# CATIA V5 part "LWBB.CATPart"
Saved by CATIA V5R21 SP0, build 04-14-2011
Part number: LWBB.SLDPRT
Bounding box of the stored display mesh (mm): x 1.55 to 5.05, y 3.678 to 6.478, z -1.805 to -0.004
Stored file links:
  C:\Users\user\Desktop\LWBB\LWBB.CATPart
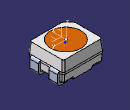
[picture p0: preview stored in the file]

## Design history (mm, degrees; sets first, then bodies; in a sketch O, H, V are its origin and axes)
AxisSystem1: origin (3.2985, 5.0752, -0.0046), X (0, -1, 0), Y (1, 0, 0), Z (0, 0, 1)
Set1
  DatumSurface1 to DatumSurface120
  Line1: stored without definition
  Circle1: stored without definition
  Line2: stored without definition
  Circle2: stored without definition
  Line3 to Line38: stored without definition
  Circle3: stored without definition
  Line39: stored without definition
  Circle4: stored without definition
  Line40 to Line43: stored without definition
  Circle5: stored without definition
  Circle6: stored without definition
  Line44 to Line46: stored without definition
  Circle7: stored without definition
  Line47: stored without definition
  Circle8: stored without definition
  Line48 to Line50: stored without definition
  Circle9 to Circle11: stored without definition
  Line51: stored without definition
  Circle12: stored without definition
  Line52: stored without definition
  Circle13 to Circle15: stored without definition
  Line53: stored without definition
  Circle16: stored without definition
  Line54: stored without definition
  Circle17 to Circle19: stored without definition
  Line55: stored without definition
  Circle20: stored without definition
  Line56: stored without definition
  Circle21 to Circle23: stored without definition
  Line57: stored without definition
  Circle24: stored without definition
  Line58: stored without definition
  Circle25: stored without definition
  Circle26: stored without definition
  Line59 to Line62: stored without definition
  Circle27: stored without definition
  Circle28: stored without definition
  Line63 to Line66: stored without definition
  Circle29: stored without definition
  Circle30: stored without definition
  Line67: stored without definition
  Circle31: stored without definition
  Line68: stored without definition
  Circle32: stored without definition
  Line69 to Line72: stored without definition
  Circle33: stored without definition
  Line73: stored without definition
  Circle34: stored without definition
  Circle35: stored without definition
  Line74: stored without definition
  Circle36: stored without definition
  Line75 to Line78: stored without definition
  Circle37: stored without definition
  Line79: stored without definition
  Circle38: stored without definition
  Line80 to Line82: stored without definition
  Circle39: stored without definition
  Line83: stored without definition
  Circle40: stored without definition
  Line84 to Line86: stored without definition
  Circle41: stored without definition
  Line87: stored without definition
  Circle42: stored without definition
  Line88 to Line90: stored without definition
  Circle43: stored without definition
  Line91: stored without definition
  Circle44: stored without definition
  Circle45: stored without definition
  Line92: stored without definition
  Circle46: stored without definition
  Line93 to Line95: stored without definition
  Circle47: stored without definition
  Line96: stored without definition
  Circle48: stored without definition
  Circle49: stored without definition
  Line97: stored without definition
  Circle50: stored without definition
  Line98 to Line100: stored without definition
  Circle51: stored without definition
  Line101: stored without definition
  Circle52: stored without definition
  Line102 to Line104: stored without definition
  Circle53: stored without definition
  Line105: stored without definition
  Circle54: stored without definition
  Line106 to Line108: stored without definition
  Circle55: stored without definition
  Line109: stored without definition
  Circle56: stored without definition
  Line110 to Line112: stored without definition
  Circle57: stored without definition
  Line113: stored without definition
  Circle58: stored without definition
  Line114: stored without definition
  Circle59: stored without definition
  Line115: stored without definition
  Circle60: stored without definition
  Line116 to Line118: stored without definition
  Circle61: stored without definition
  Line119: stored without definition
  Circle62: stored without definition
  Line120 to Line132: stored without definition
  Circle63: stored without definition
  Line133: stored without definition
  Circle64: stored without definition
  Line134 to Line136: stored without definition
  Circle65: stored without definition
  Line137: stored without definition
  Circle66: stored without definition
  Line138: stored without definition
  Circle67: stored without definition
  Line139: stored without definition
  Circle68: stored without definition
  Line140 to Line143: stored without definition
  Circle69: stored without definition
  Circle70: stored without definition
  Line144 to Line153: stored without definition
  Circle71: stored without definition
  Line154: stored without definition
  Circle72: stored without definition
  Line155 to Line157: stored without definition
  Circle73: stored without definition
  Line158: stored without definition
  Circle74: stored without definition
  Line159 to Line161: stored without definition
  Circle75: stored without definition
  Line162: stored without definition
  Circle76: stored without definition
  Line163 to Line165: stored without definition
  Circle77: stored without definition
  Line166: stored without definition
  Circle78: stored without definition
  Line167 to Line169: stored without definition
  Circle79: stored without definition
  Line170: stored without definition
  Circle80: stored without definition
  Line171 to Line173: stored without definition
  Circle81: stored without definition
  Line174: stored without definition
  Circle82: stored without definition
  Line175 to Line177: stored without definition
  Circle83: stored without definition
  Line178: stored without definition
  Circle84: stored without definition
  Line179 to Line181: stored without definition
  Circle85: stored without definition
  Line182: stored without definition
  Circle86: stored without definition
  Line183 to Line185: stored without definition
  Circle87: stored without definition
  Line186: stored without definition
  Circle88: stored without definition
  Line187 to Line189: stored without definition
  Circle89: stored without definition
  Line190: stored without definition
  Circle90: stored without definition
  Line191 to Line193: stored without definition
  Circle91: stored without definition
  Line194: stored without definition
  Circle92: stored without definition
  Line195 to Line197: stored without definition
  Circle93: stored without definition
  Line198: stored without definition
  Circle94: stored without definition
  Line199 to Line201: stored without definition
  Circle95: stored without definition
  Line202: stored without definition
  Circle96: stored without definition
  Line203 to Line205: stored without definition
  Circle97: stored without definition
  Line206: stored without definition
  Circle98: stored without definition
  Line207 to Line209: stored without definition
  Circle99: stored without definition
  Line210: stored without definition
  Circle100: stored without definition
  Line211 to Line213: stored without definition
  Circle101: stored without definition
  Line214: stored without definition
  Circle102: stored without definition
  Line215 to Line217: stored without definition
  Circle103: stored without definition
  Line218: stored without definition
  Circle104: stored without definition
  Line219 to Line221: stored without definition
  Circle105: stored without definition
  Line222: stored without definition
  Circle106: stored without definition
  Line223 to Line225: stored without definition
  Circle107: stored without definition
  Line226: stored without definition
  Circle108: stored without definition
  Line227 to Line229: stored without definition
  Circle109: stored without definition
  Line230: stored without definition
  Circle110: stored without definition
  Line231 to Line241: stored without definition
  DatumSurface121 to DatumSurface179
  Circle111: stored without definition
  Line242: stored without definition
  Circle112: stored without definition
  Line243: stored without definition
  Circle113 to Circle115: stored without definition
  Line244: stored without definition
  Circle116: stored without definition
  Line245 to Line248: stored without definition
  Circle117: stored without definition
  Circle118: stored without definition
  Line249 to Line251: stored without definition
  Circle119: stored without definition
  Line252: stored without definition
  Circle120: stored without definition
  Line253 to Line256: stored without definition
  Circle121: stored without definition
  Circle122: stored without definition
  Line257 to Line261: stored without definition
  Circle123: stored without definition
  Circle124: stored without definition
  Line262 to Line265: stored without definition
  Circle125 to Circle128: stored without definition
  Line266 to Line270: stored without definition
  Circle129: stored without definition
  Circle130: stored without definition
  Line271 to Line274: stored without definition
  Circle131: stored without definition
  Circle132: stored without definition
  Line275 to Line277: stored without definition
  Circle133: stored without definition
  Circle134: stored without definition
  Line278 to Line282: stored without definition
  Circle135: stored without definition
  Circle136: stored without definition
  Line283 to Line286: stored without definition
  Circle137: stored without definition
  Circle138: stored without definition
  Line287 to Line289: stored without definition
  Circle139: stored without definition
  Circle140: stored without definition
  Line290 to Line293: stored without definition
  Circle141: stored without definition
  Circle142: stored without definition
  Line294 to Line298: stored without definition
  Circle143: stored without definition
  Circle144: stored without definition
  Line299 to Line302: stored without definition
  Circle145: stored without definition
  Circle146: stored without definition
  Line303 to Line306: stored without definition
  Circle147: stored without definition
  Circle148: stored without definition
  Line307 to Line310: stored without definition
  Circle149: stored without definition
  Circle150: stored without definition
  Line311: stored without definition
  Circle151: stored without definition
  Line312: stored without definition
  Circle152 to Circle154: stored without definition
  Line313 to Line316: stored without definition
  Circle155: stored without definition
  Circle156: stored without definition
  Line317 to Line320: stored without definition
  Circle157: stored without definition
  Circle158: stored without definition
  Line321: stored without definition
  Line322: stored without definition
  Circle159: stored without definition
  Circle160: stored without definition
  Line323 to Line325: stored without definition
  Circle161: stored without definition
  Circle162: stored without definition
  Line326 to Line330: stored without definition
  Circle163: stored without definition
  Circle164: stored without definition
  Line331 to Line334: stored without definition
  Circle165: stored without definition
  Circle166: stored without definition
  Line335 to Line337: stored without definition
  Circle167: stored without definition
  Circle168: stored without definition
  Line338 to Line342: stored without definition
  Circle169: stored without definition
  Line343 to Line345: stored without definition
  Circle170: stored without definition
  Line346 to Line352: stored without definition
  DatumSurface180 to DatumSurface389
  Circle171: stored without definition
  Circle172: stored without definition
  Line353: stored without definition
  Line354: stored without definition
  Circle173: stored without definition
  Circle174: stored without definition
  DatumCurve1
  Line355: stored without definition
  Line356: stored without definition
  Circle175: stored without definition
  Line357: stored without definition
  DatumCurve2
  Circle176: stored without definition
  Line358: stored without definition
  Circle177 to Circle183: stored without definition
  Line359: stored without definition
  Line360: stored without definition
  Circle184 to Circle188: stored without definition
  Line361: stored without definition
  Circle189: stored without definition
  Line362: stored without definition
  Circle190 to Circle192: stored without definition
  Line363: stored without definition
  Circle193: stored without definition
  Line364: stored without definition
  Circle194 to Circle196: stored without definition
  Line365: stored without definition
  Circle197: stored without definition
  Line366: stored without definition
  Circle198 to Circle200: stored without definition
  Line367: stored without definition
  Circle201: stored without definition
  Line368: stored without definition
  Circle202 to Circle204: stored without definition
  Line369 to Line373: stored without definition
  Circle205: stored without definition
  Line374: stored without definition
  Circle206 to Circle208: stored without definition
  Line375: stored without definition
  Circle209: stored without definition
  Line376: stored without definition
  Circle210: stored without definition
  Line377 to Line379: stored without definition
  Circle211: stored without definition
  Circle212: stored without definition
  Line380 to Line383: stored without definition
  Circle213: stored without definition
  Circle214: stored without definition
  Line384 to Line388: stored without definition
  Circle215: stored without definition
  Circle216: stored without definition
  Line389 to Line391: stored without definition
  Circle217: stored without definition
  Circle218: stored without definition
  Line392: stored without definition
  Line393: stored without definition
  Circle219: stored without definition
  Circle220: stored without definition
  Line394 to Line397: stored without definition
  Circle221: stored without definition
  Circle222: stored without definition
  Line398 to Line401: stored without definition
  Circle223 to Circle226: stored without definition
  Line402 to Line405: stored without definition
  Circle227: stored without definition
  Circle228: stored without definition
  Line406 to Line409: stored without definition
  Circle229: stored without definition
  Circle230: stored without definition
  Line410 to Line413: stored without definition
  Circle231: stored without definition
  Circle232: stored without definition
  Line414 to Line417: stored without definition
  Circle233: stored without definition
  Circle234: stored without definition
  Line418 to Line422: stored without definition
  Circle235: stored without definition
  Circle236: stored without definition
  Line423 to Line426: stored without definition
  Circle237: stored without definition
  Circle238: stored without definition
  Line427 to Line429: stored without definition
  Circle239: stored without definition
  Circle240: stored without definition
  Line430 to Line433: stored without definition
  Circle241: stored without definition
  Circle242: stored without definition
  Line434 to Line438: stored without definition
  Circle243: stored without definition
  Circle244: stored without definition
  Line439 to Line441: stored without definition
  Circle245: stored without definition
  Circle246: stored without definition
  Line442 to Line445: stored without definition
  Circle247: stored without definition
  Circle248: stored without definition
  Line446 to Line450: stored without definition
  Circle249 to Circle252: stored without definition
  Line451 to Line454: stored without definition
  Circle253: stored without definition
  Circle254: stored without definition
  Line455 to Line459: stored without definition
  Circle255 to Circle257: stored without definition
  Line460: stored without definition
  Circle258: stored without definition
  Line461 to Line464: stored without definition
  Circle259: stored without definition
  Line465: stored without definition
  Circle260: stored without definition
  Line466 to Line468: stored without definition
  Circle261: stored without definition
  Line469: stored without definition
  Circle262: stored without definition
  Line470 to Line472: stored without definition
  Circle263: stored without definition
  Line473: stored without definition
  Circle264: stored without definition
  Line474 to Line476: stored without definition
  Circle265: stored without definition
  Line477: stored without definition
  Circle266: stored without definition
  Line478 to Line480: stored without definition
  Circle267: stored without definition
  Line481: stored without definition
  Circle268: stored without definition
  Line482 to Line484: stored without definition
  Circle269: stored without definition
  Line485: stored without definition
  Circle270: stored without definition
  Line486 to Line488: stored without definition
  Circle271: stored without definition
  Line489: stored without definition
  Circle272: stored without definition
  Line490 to Line492: stored without definition
  Circle273: stored without definition
  Line493: stored without definition
  Circle274: stored without definition
  Line494 to Line496: stored without definition
  Circle275: stored without definition
  Line497: stored without definition
  Circle276: stored without definition
  Line498 to Line500: stored without definition
  Circle277: stored without definition
  Line501: stored without definition
  Circle278: stored without definition
  Line502 to Line509: stored without definition
  Circle279: stored without definition
  Circle280: stored without definition
  DatumCurve3
  DatumCurve4
  Circle281: stored without definition
  Line510 to Line512: stored without definition
  DatumCurve5
  Circle282: stored without definition
  Circle283: stored without definition
  DatumCurve6
  DatumCurve7
  Line513: stored without definition
  DatumCurve8
  Line514: stored without definition
  Circle284: stored without definition
  DatumCurve9
  Circle285: stored without definition
  Line515: stored without definition
  Circle286: stored without definition
  Line516: stored without definition
  DatumCurve10
  Circle287: stored without definition
  Circle288: stored without definition
  Line517: stored without definition
  Line518: stored without definition
  DatumCurve11
  Circle289: stored without definition
  DatumCurve12
  Line519: stored without definition
  Circle290: stored without definition
  Line520: stored without definition
  DatumCurve13
  Circle291: stored without definition
  Line521: stored without definition
  Circle292: stored without definition
  Line522: stored without definition
  Line523: stored without definition
  Circle293: stored without definition
  Line524: stored without definition
  DatumCurve14
  Circle294: stored without definition
  Line525: stored without definition
  Line526: stored without definition
  Circle295: stored without definition
  Circle296: stored without definition
  Line527 to Line529: stored without definition
  DatumCurve15
  Line530: stored without definition
  Circle297: stored without definition
  DatumCurve16
  Line531: stored without definition
  Circle298: stored without definition
  Line532: stored without definition
  Line533: stored without definition
  DatumCurve17
  Circle299: stored without definition
  Line534: stored without definition
  Line535: stored without definition
  Circle300: stored without definition
  Circle301: stored without definition
  Line536: stored without definition
  Line537: stored without definition
  Circle302: stored without definition
  Line538: stored without definition
  Circle303: stored without definition
  Line539 to Line542: stored without definition
  DatumCurve18
  Line543: stored without definition
  DatumCurve19
  Circle304: stored without definition
  DatumCurve20
  Line544: stored without definition
  Circle305: stored without definition
  Line545: stored without definition
  DatumCurve21
  DatumCurve22
  Line546: stored without definition
  Circle306 to Circle308: stored without definition
  Line547: stored without definition
  Circle309: stored without definition
  Line548: stored without definition
  Line549: stored without definition
  DatumCurve23
  Line550 to Line555: stored without definition
  Circle310: stored without definition
  Line556: stored without definition
  Circle311: stored without definition
  Line557 to Line559: stored without definition
  Circle312: stored without definition
  Line560: stored without definition
  Circle313: stored without definition
  Line561 to Line580: stored without definition
  Circle314: stored without definition
  Line581: stored without definition
  DatumCurve24
  Line582: stored without definition
  DatumCurve25
  Line583 to Line588: stored without definition
  Circle315: stored without definition
  Line589: stored without definition
  Circle316: stored without definition
  Line590 to Line592: stored without definition
  Circle317: stored without definition
  Line593: stored without definition
  Circle318: stored without definition
  Line594 to Line596: stored without definition
  Circle319: stored without definition
  Line597: stored without definition
  Circle320: stored without definition
  Line598 to Line600: stored without definition
  Circle321: stored without definition
  Line601: stored without definition
  Circle322: stored without definition
  Line602 to Line604: stored without definition
  Circle323: stored without definition
  Line605: stored without definition
  Circle324: stored without definition
  Circle325: stored without definition
  Line606: stored without definition
  Circle326: stored without definition
  Line607 to Line609: stored without definition
  Circle327: stored without definition
  Line610: stored without definition
  Circle328: stored without definition
  Circle329: stored without definition
  Line611: stored without definition
  Circle330: stored without definition
  Line612 to Line614: stored without definition
  Circle331: stored without definition
  Line615: stored without definition
  Circle332: stored without definition
  Line616 to Line618: stored without definition
  Circle333: stored without definition
  Line619: stored without definition
  Circle334: stored without definition
  Line620 to Line622: stored without definition
  Circle335: stored without definition
  Line623: stored without definition
  Circle336: stored without definition
  Line624 to Line626: stored without definition
  Circle337: stored without definition
  Line627: stored without definition
  Circle338: stored without definition
  Line628 to Line634: stored without definition
  Circle339: stored without definition
  DatumCurve26
  Line635: stored without definition
  DatumCurve27
  Line636: stored without definition
  Line637: stored without definition
  DatumCurve28
  Line638: stored without definition
  DatumCurve29
  Circle340: stored without definition
  Line639: stored without definition
  DatumCurve30
  Line640 to Line642: stored without definition
  DatumCurve31
  Line643 to Line645: stored without definition
  DatumCurve32
  Circle341: stored without definition
  Line646 to Line650: stored without definition
  DatumCurve33
  Circle342: stored without definition
  Line651 to Line664: stored without definition
  Circle343: stored without definition
  Line665: stored without definition
  Circle344: stored without definition
  Line666: stored without definition
  Circle345: stored without definition
  Line667: stored without definition
  Circle346: stored without definition
  Line668: stored without definition
  Circle347: stored without definition
  Line669: stored without definition
  Circle348: stored without definition
  Line670: stored without definition
  Circle349: stored without definition
  DatumCurve34
  Line671 to Line674: stored without definition
  Circle350: stored without definition
  Line675 to Line677: stored without definition
  Circle351: stored without definition
  Line678: stored without definition
  Line679: stored without definition
  Circle352: stored without definition
  Line680 to Line683: stored without definition
  Circle353: stored without definition
  Line684: stored without definition
  Line685: stored without definition
  Circle354: stored without definition
  Line686 to Line688: stored without definition
  Circle355: stored without definition
  Line689 to Line692: stored without definition
  Circle356: stored without definition
  Line693 to Line702: stored without definition
  DatumCurve35
  Line703: stored without definition
  DatumCurve36
  Circle357: stored without definition
  Line704: stored without definition
  Line705: stored without definition
  Circle358: stored without definition
  Point1 "几何中心&光学中心（测试原点）": type Center, Curve edge of DatumSurface344
  Point2: (0.0299, 0.0242, -0.1878), relative to Point1, in AxisSystem1
Body1 (main body)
